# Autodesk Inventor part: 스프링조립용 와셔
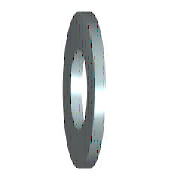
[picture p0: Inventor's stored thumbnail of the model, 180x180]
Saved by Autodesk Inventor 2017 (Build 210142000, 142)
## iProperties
IsCustomPart: 1
Created: 2012-02
Part Number: 스프링조립용 와셔
Material: 강철, 연강
Description: 평면 와셔
Document SubType Name: Modeling
Standard: KS B 1326
Designer: mduedu
Standards Organization: KS
Language: ko-KR
Size Designation: 12x24
Categories: <MemberInstance><Categories><Category DisplayName="조임쇠" InternalName="e4da775c-781d-43d5-af7c-5136215cf5a6" Mnemonic="FSTN"><Category DisplayName="와셔" InternalN
Density: 7.85 g/cm^3
Appearance: 파란색 - 벽 페인트 - 광택
Mass: 5.38854 g
Surface Area: 8.71478 cm^2
Volume: 0.686438 cm^3
Author: mduedu
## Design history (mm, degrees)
sketch "스케치"
  geometry: C1 r 12 at (0, 0); C2 r 7 at (0, 0); 1 further point
  constraints: 2 centre point, 2 coincident
  dimensions: "d0" = 14 diameter of C2 (= SD1); "d1" = 24 diameter of C1 (= SD2)
extrude "본체" new body sketch "스케치" distance "d2" = 2.3 (= SD); taper "d3" = 0 deg
workaxis "Work Axis1"
workplane "Work Plane1"
body "Solid1"
other parameters: "SD1" = 14 [user parameter; used in 1 equation term], "SD2" = 24 [user parameter; used in 1 equation term], "SD" = 2.3 [user parameter; used in 1 equation term], "d4" = 0, "d5" = 0, "d6" = 0, "d7" = 0, "NND" = 12 [user parameter]
